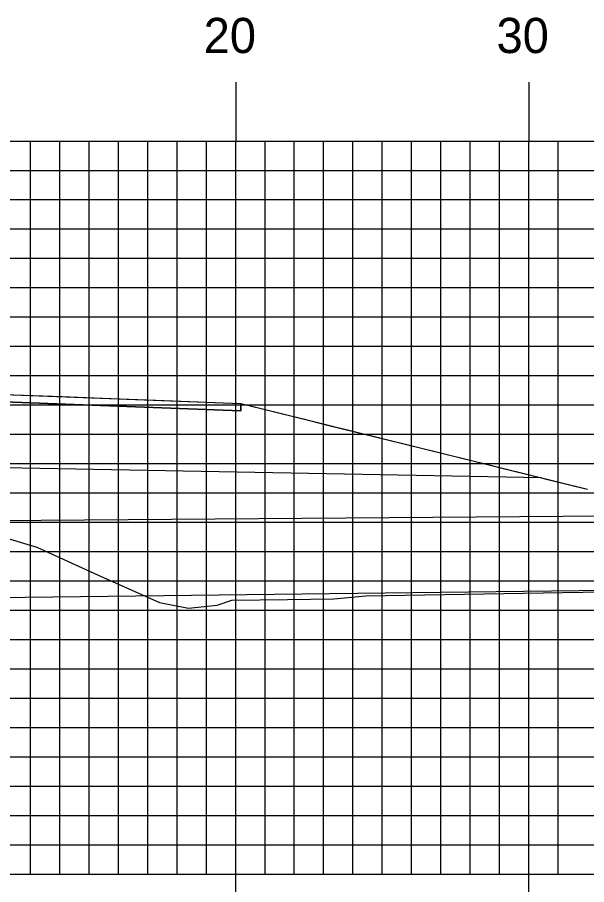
# Model space of a CAD drawing. Extents: x 1823571 to 1823914, y 442310 to 442530.
# Drawn here: x 1823749.45 to 1823768.87, y 442327.75 to 442357.33 of the extents above; entities that cross this region are included whole.
import ezdxf

# ---------------------------------------------------------------- set-up
doc = ezdxf.new("R2010")
doc.units = 0
for name, color, linetype in [('D_Drainage_Culvert', 7, 'Continuous'), ('D_Roadway_Centerline', 7, 'Continuous'), ('D_Roadway_Edge_Shoulder', 7, 'Continuous'), ('D_Roadway_SlopeLines', 7, 'Continuous'), ('D_Roadway_SubGrade', 7, 'Continuous'), ('H_V ANNOTATION', 7, 'Continuous'), ('MAJOR', 7, 'Continuous'), ('MINOR', 7, 'Continuous'), ('S_Roadway_Centerline', 7, 'Continuous')]:
    doc.layers.add(name, color=color, linetype=linetype)

msp = doc.modelspace()

# ---------------------------------------------------------------- linework, layer by layer
at = {"layer": 'D_Drainage_Culvert'}
for p, q in [((1823695.626, 442339.755), (1823775.623, 442340.383)), ((1823775.653, 442337.862), (1823695.648, 442336.899))]:
    msp.add_line(p, q, dxfattribs=at)
at = {"layer": 'D_Roadway_Centerline'}
msp.add_lwpolyline([(1823749.004, 442344.473), (1823750.983, 442344.396), (1823752.344, 442344.343), (1823753.872, 442344.284), (1823756.196, 442344.194), (1823756.477, 442344.183), (1823757.074, 442344.16), (1823759.203, 442343.634), (1823759.99, 442343.439), (1823762.585, 442342.798), (1823765.596, 442342.054), (1823765.885, 442341.983), (1823767.336, 442341.625), (1823767.535, 442341.576), (1823767.636, 442341.551), (1823768.842, 442341.253)], dxfattribs=at)
at = {"layer": 'D_Roadway_Edge_Shoulder'}
msp.add_lwpolyline([(1823749.004, 442344.473), (1823757.073, 442344.16), (1823757.073, 442343.91), (1823749.004, 442344.223)], close=True, dxfattribs=at)
at = {"layer": 'D_Roadway_SlopeLines'}
msp.add_lwpolyline([(1823757.073, 442344.16), (1823768.9, 442341.238)], dxfattribs=at)
at = {"layer": 'D_Roadway_SubGrade'}
msp.add_lwpolyline([(1823724.796, 442341.953), (1823707.283, 442341.592), (1823716.727, 442344.127), (1823716.727, 442343.877), (1823724.796, 442344.203), (1823736.9, 442344.453), (1823749.004, 442344.223), (1823757.073, 442343.91), (1823757.073, 442344.16), (1823767.336, 442341.625), (1823749.004, 442341.973), (1823736.9, 442342.203)], close=True, dxfattribs=at)
at = {"layer": 'MAJOR'}
for p, q in [((1823756.9, 442355.119), (1823756.9, 442353.115)), ((1823766.9, 442355.119), (1823766.9, 442353.115)), ((1823596.9, 442353.115), (1823876.9, 442353.115)), ((1823756.9, 442328.115), (1823756.9, 442353.115)), ((1823766.9, 442328.115), (1823766.9, 442353.115)), ((1823596.9, 442348.115), (1823876.9, 442348.115)), ((1823596.9, 442343.115), (1823876.9, 442343.115)), ((1823596.9, 442338.115), (1823876.9, 442338.115)), ((1823596.9, 442333.115), (1823876.9, 442333.115)), ((1823596.9, 442328.115), (1823876.9, 442328.115)), ((1823596.9, 442328.115), (1823876.9, 442328.115)), ((1823756.9, 442326.111), (1823756.9, 442328.115)), ((1823766.9, 442326.111), (1823766.9, 442328.115))]:
    msp.add_line(p, q, dxfattribs=at)
at = {"layer": 'MINOR'}
for p, q in [((1823749.9, 442328.115), (1823749.9, 442353.115)), ((1823750.9, 442328.115), (1823750.9, 442353.115)), ((1823751.9, 442328.115), (1823751.9, 442353.115)), ((1823752.9, 442328.115), (1823752.9, 442353.115)), ((1823753.9, 442328.115), (1823753.9, 442353.115)), ((1823754.9, 442328.115), (1823754.9, 442353.115)), ((1823755.9, 442328.115), (1823755.9, 442353.115)), ((1823757.9, 442328.115), (1823757.9, 442353.115)), ((1823758.9, 442328.115), (1823758.9, 442353.115)), ((1823759.9, 442328.115), (1823759.9, 442353.115)), ((1823760.9, 442328.115), (1823760.9, 442353.115)), ((1823761.9, 442328.115), (1823761.9, 442353.115)), ((1823762.9, 442328.115), (1823762.9, 442353.115)), ((1823763.9, 442328.115), (1823763.9, 442353.115)), ((1823764.9, 442328.115), (1823764.9, 442353.115)), ((1823765.9, 442328.115), (1823765.9, 442353.115)), ((1823767.9, 442328.115), (1823767.9, 442353.115)), ((1823596.9, 442352.115), (1823876.9, 442352.115)), ((1823596.9, 442351.115), (1823876.9, 442351.115)), ((1823596.9, 442350.115), (1823876.9, 442350.115)), ((1823596.9, 442349.115), (1823876.9, 442349.115)), ((1823596.9, 442347.115), (1823876.9, 442347.115)), ((1823596.9, 442346.115), (1823876.9, 442346.115)), ((1823596.9, 442345.115), (1823876.9, 442345.115)), ((1823596.9, 442344.115), (1823876.9, 442344.115)), ((1823596.9, 442342.115), (1823876.9, 442342.115)), ((1823596.9, 442341.115), (1823876.9, 442341.115)), ((1823596.9, 442340.115), (1823876.9, 442340.115)), ((1823596.9, 442339.115), (1823876.9, 442339.115)), ((1823596.9, 442337.115), (1823876.9, 442337.115)), ((1823596.9, 442336.115), (1823876.9, 442336.115)), ((1823596.9, 442335.115), (1823876.9, 442335.115)), ((1823596.9, 442334.115), (1823876.9, 442334.115)), ((1823596.9, 442332.115), (1823876.9, 442332.115)), ((1823596.9, 442331.115), (1823876.9, 442331.115)), ((1823596.9, 442330.115), (1823876.9, 442330.115)), ((1823596.9, 442329.115), (1823876.9, 442329.115))]:
    msp.add_line(p, q, dxfattribs=at)
at = {"layer": 'S_Roadway_Centerline'}
msp.add_lwpolyline([(1823748.703, 442339.678), (1823750.118, 442339.264), (1823752.184, 442338.314), (1823754.298, 442337.377), (1823755.289, 442337.178), (1823756.266, 442337.283), (1823756.772, 442337.458), (1823758.668, 442337.476), (1823760.242, 442337.496), (1823761.343, 442337.598), (1823779.492, 442337.907), (1823792.942, 442338.071)], dxfattribs=at)

# ---------------------------------------------------------------- texts
at = {"layer": 'H_V ANNOTATION'}
for s, p in [('20', (1823755.808, 442356.115)), ('30', (1823765.797, 442356.115))]:
    msp.add_text(s, height=1.2, dxfattribs=at).set_placement(p)

doc.saveas('drawing.dxf')
